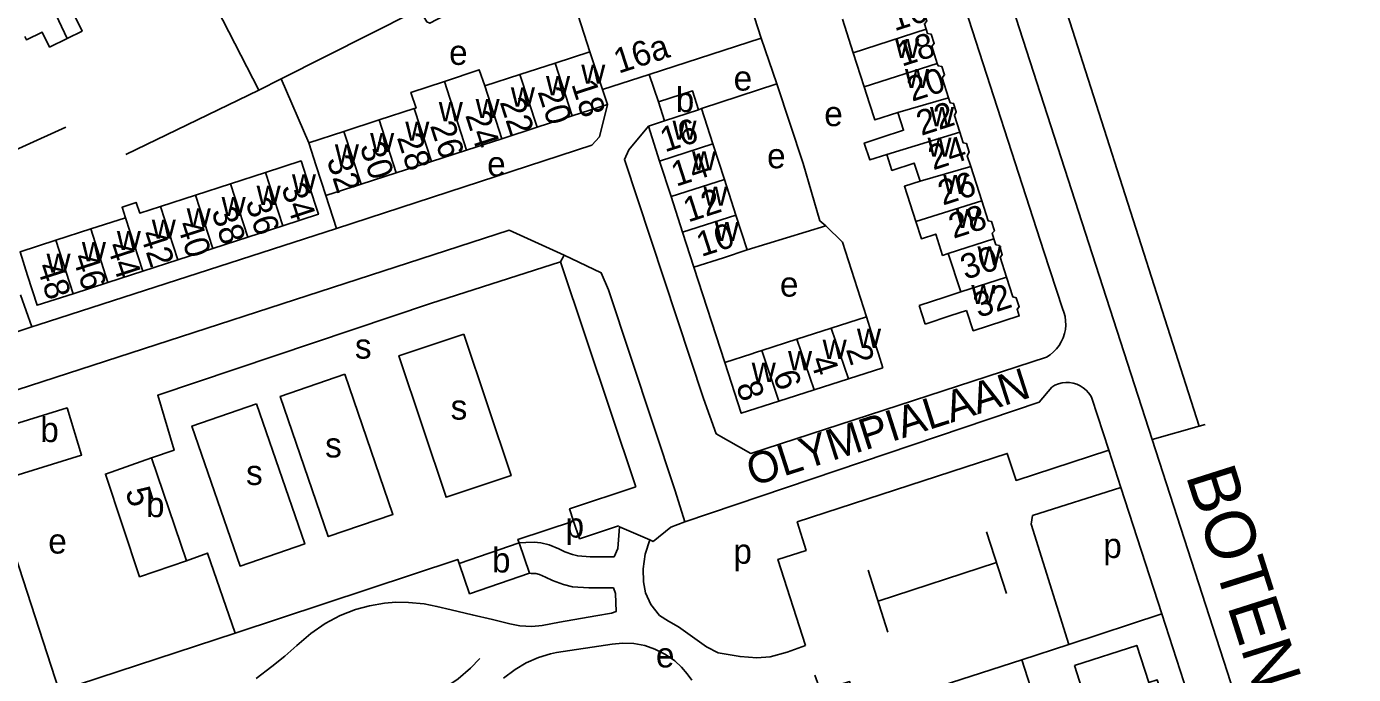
# Model space of a CAD drawing. Extents: x 157569 to 159501, y 382907 to 384670.
# Drawn here: x 159236.8 to 159450, y 383198.5 to 383302.6 of the extents above; entities that cross this region are included whole.
import ezdxf

# ---------------------------------------------------------------- set-up
doc = ezdxf.new("R2010")
doc.units = 0
for name, color, linetype in [('BLT_Basislijn', 7, 'Continuous'), ('BLT_Bebouwing', 7, 'Continuous'), ('BLT_Centroide', 7, 'Continuous'), ('BLT_Huisnummer', 7, 'Continuous'), ('BLT_Huisnummer_ tussenligend', 7, 'Continuous'), ('BLT_Onderverdeling_panden', 7, 'Continuous'), ('BLT_Straatnaam', 7, 'Continuous'), ('BLT_Straatnaam_hoofdweg', 7, 'Continuous'), ('BLT_Vlakafsluiter', 7, 'Continuous')]:
    doc.layers.add(name, color=color, linetype=linetype)

msp = doc.modelspace()

# ---------------------------------------------------------------- linework, layer by layer
at = {"layer": 'BLT_Basislijn'}
for p, q in [((159379.54, 383354.13), (159408.56, 383264.22)), ((159376.06, 383341.3), (159400.22, 383266.41)), ((159425.15, 383238.36), (159395.57, 383330.94)), ((159264.77, 383310.5), (159274.09, 383292.35)), ((159354.8, 383300.68), (159357.32, 383293.39)), ((159338.28, 383290.45), (159336.8, 383294.86)), ((159252.74, 383282.03), (159274.09, 383292.35)), ((159277.69, 383294.17), (159274.09, 383292.35)), ((159277.69, 383294.17), (159282.11, 383283.9)), ((159357.32, 383293.39), (159345.21, 383289.38)), ((159284.86, 383275.41), (159286.59, 383270.15)), ((159352.52, 383266.71), (159365.2, 383270.54)), ((159322.54, 383264.76), (159323.12, 383265.83)), ((159400.22, 383266.41), (159403.2, 383257.26)), ((159343.98, 383263.9), (159348.96, 383248.6)), ((159408.56, 383264.22), (159417.61, 383236.25)), ((159237.62, 383254.3), (159235.8, 383259.46)), ((159192.4, 383239.63), (159237.62, 383254.3)), ((159407.94, 383242.87), (159410.65, 383234.51)), ((159417.61, 383236.25), (159437.39, 383175.1)), ((159410.65, 383234.51), (159412.59, 383228.53)), ((159412.59, 383228.53), (159419.16, 383208.22)), ((159394.22, 383211.51), (159390.99, 383221.39)), ((159373.57, 383210.25), (159392.61, 383216.45)), ((159371.98, 383215.21), (159375.17, 383205.29)), ((159404.23, 383203.27), (159419.16, 383208.22)), ((159419.16, 383208.22), (159427.45, 383182.63)), ((159396.7, 383200.83), (159404.23, 383203.27)), ((159396.7, 383200.83), (159404.81, 383175.08))]:
    msp.add_line(p, q, dxfattribs=at)
for points in [[(159322.28, 383313.99), (159301.55, 383303.11), (159301.08, 383303.33), (159300.1, 383304.91), (159299.07, 383304.91), (159277.69, 383294.17)], [(159357.32, 383293.39), (159361.54, 383280.58), (159364.22, 383271.37), (159365.2, 383270.54)], [(159286.59, 383270.15), (159327.57, 383283.52), (159328.82, 383284.86), (159330.08, 383290.04)], [(159243.1, 383286.39), (159229.71, 383280.36), (159228.83, 383279.98)], [(159336.67, 383286.59), (159333.53, 383282.75), (159332.82, 383281.2), (159345.53, 383242.79)], [(159227.11, 383241.57), (159314.29, 383269.88), (159323.12, 383265.83)], [(159237.62, 383254.3), (159238.66, 383254.64), (159286.59, 383270.15)], [(159365.2, 383270.54), (159367.88, 383267.95), (159371.72, 383255.94)], [(159256.84, 383233.29), (159260.47, 383234.5), (159257.84, 383243.34), (159301.65, 383258.08), (159322.54, 383264.76)], [(159334.65, 383228.6), (159322.54, 383264.76)], [(159323.12, 383265.83), (159329.1, 383262.99), (159330.27, 383260.28), (159340.96, 383227.96), (159342.53, 383222.99)], [(159400.62, 383249.48), (159401.21, 383249.85), (159401.75, 383250.29), (159402.24, 383250.79), (159402.66, 383251.34), (159403.02, 383251.93), (159403.32, 383252.57), (159403.53, 383253.23), (159403.67, 383253.91), (159403.73, 383254.6), (159403.71, 383255.3), (159403.61, 383255.99), (159403.43, 383256.66), (159403.2, 383257.26)], [(159307.05, 383253.15), (159314.61, 383230.43), (159304.16, 383226.95), (159296.6, 383249.67), (159307.05, 383253.15)], [(159345.53, 383242.79), (159347.54, 383237.16), (159353.11, 383233.98), (159400.62, 383249.48)], [(159287.93, 383246.7), (159295.63, 383224.17), (159285.25, 383220.62), (159277.54, 383243.15), (159287.93, 383246.7)], [(159401.47, 383244.66), (159401.99, 383244.95), (159402.55, 383245.17), (159403.13, 383245.31), (159403.73, 383245.38), (159404.33, 383245.36), (159404.92, 383245.27), (159405.49, 383245.1), (159406.04, 383244.85), (159406.54, 383244.53), (159407.01, 383244.15), (159407.41, 383243.71), (159407.75, 383243.22), (159407.94, 383242.87)], [(159401.47, 383244.66), (159399.46, 383242.2), (159342.53, 383222.99)], [(159227.11, 383241.57), (159242, 383195.83)], [(159273.73, 383241.94), (159281.46, 383219.46), (159271.07, 383215.88), (159263.33, 383238.37), (159273.73, 383241.94)], [(159410.65, 383234.51), (159395.75, 383229.65), (159394.33, 383234), (159360.6, 383222.99), (159362, 383218.41), (159357.49, 383216.95), (159361.94, 383203.13)], [(159324.65, 383223.12), (159324.01, 383225.06), (159334.65, 383228.6)], [(159404.23, 383203.27), (159398.17, 383222.63), (159398.4, 383223.99), (159412.59, 383228.53)], [(159315.9, 383219.6), (159315.71, 383220.16), (159324.65, 383223.12)], [(159324.65, 383223.12), (159325.62, 383220.27), (159331.87, 383222.34)], [(159331.75, 383218.71), (159332.06, 383222.2)], [(159331.87, 383222.34), (159332.06, 383222.2)], [(159332.06, 383222.2), (159336.92, 383220.08)], [(159337.46, 383219.85), (159340.3, 383222.12), (159342.53, 383222.99)], [(159331.75, 383218.71), (159331.17, 383217.37), (159327.3, 383217.37), (159325.33, 383217.52), (159324.47, 383217.74), (159323.25, 383218.16), (159322.3, 383218.66), (159320.75, 383219.31), (159319.37, 383219.63), (159318.34, 383219.72), (159316.96, 383219.68), (159315.9, 383219.6)], [(159336.92, 383220.08), (159336.14, 383217.79), (159335.82, 383215.46), (159335.89, 383213.38), (159336.23, 383211.57), (159337.08, 383209.7), (159338.45, 383207.97), (159339.93, 383207.03), (159341.54, 383206.13), (159345.99, 383202.89)], [(159336.92, 383220.08), (159337.46, 383219.85)], [(159262.48, 383216.74), (159265.86, 383217.99), (159270.27, 383205.11)], [(159270.27, 383205.11), (159306.06, 383216.96), (159306.29, 383216.3)], [(159331.41, 383211.48), (159331.07, 383212.37), (159327.11, 383212.37), (159324.5, 383212.56), (159323.02, 383212.95), (159321.27, 383213.55), (159320.17, 383214.13), (159319.2, 383214.54), (159318.58, 383214.68), (159318.2, 383214.71), (159317.84, 383214.7), (159317.57, 383214.75)], [(159273.68, 383197.83), (159276.2, 383199.73), (159278.26, 383201.4), (159280.22, 383203.12), (159282.47, 383205.08), (159284.77, 383206.66), (159287.18, 383207.93), (159289.62, 383208.89), (159291.87, 383209.51), (159294.3, 383209.92), (159296.09, 383210.07), (159298.16, 383210.06), (159300.64, 383209.82), (159302.69, 383209.42), (159305, 383208.87), (159308.38, 383208.07), (159311.65, 383207.29), (159314.4, 383206.63), (159316.04, 383206.3), (159317.95, 383206.2), (159319.6, 383206.36), (159322.38, 383206.86), (159328.24, 383207.89), (159330.73, 383208.3), (159331.51, 383208.61), (159331.41, 383211.48)], [(159242, 383195.83), (159270.27, 383205.11)], [(159313.38, 383197.88), (159315.25, 383199.3), (159317.03, 383200.33), (159319.02, 383201.2), (159320.96, 383201.79), (159321.93, 383201.99), (159330.86, 383203.37), (159332.49, 383203.52), (159334.36, 383203.44), (159336.08, 383203.11), (159337.71, 383202.56), (159339.45, 383201.68), (159340.91, 383200.64), (159342.01, 383199.63), (159342.91, 383198.58), (159343.63, 383197.56)], [(159361.94, 383203.13), (159358.99, 383202.07), (159356.24, 383201.33), (159354.12, 383201.15), (159351.4, 383201.34), (159347.86, 383201.96), (159345.99, 383202.89)], [(159281.32, 383196.59), (159283.97, 383195.19), (159287.47, 383194.01), (159291.12, 383193.43), (159294.66, 383193.44), (159298.77, 383194.14), (159301.59, 383195.19), (159303.96, 383196.35), (159306.09, 383197.79), (159308.09, 383199.47), (159309.58, 383201.02)], [(159363.44, 383198.36), (159364.34, 383195.82), (159369, 383197.34), (159370.57, 383192.4), (159396.7, 383200.83)]]:
    msp.add_lwpolyline(points, dxfattribs=at)
at = {"layer": 'BLT_Bebouwing'}
for p, q in [((159346.57, 383326.35), (159354.8, 383300.68)), ((159327.29, 383298.52), (159322.28, 383313.99)), ((159336.8, 383294.86), (159354.8, 383300.68)), ((159321.68, 383296.7), (159327.29, 383298.52)), ((159316.03, 383294.88), (159321.68, 383296.7)), ((159310.38, 383293.05), (159316.03, 383294.88)), ((159329.33, 383292.44), (159336.8, 383294.86)), ((159330.08, 383290.04), (159329.33, 383292.44)), ((159324.43, 383288.21), (159330.08, 383290.04)), ((159338.28, 383290.45), (159339.25, 383287.42)), ((159293.42, 383287.56), (159299.07, 383289.39)), ((159318.78, 383286.38), (159324.43, 383288.21)), ((159344.75, 383289.21), (159345.21, 383289.38)), ((159345.21, 383289.38), (159347.04, 383283.71)), ((159282.11, 383283.9), (159287.77, 383285.73)), ((159287.77, 383285.73), (159293.42, 383287.56)), ((159313.13, 383284.55), (159318.78, 383286.38)), ((159336.67, 383286.59), (159339.25, 383287.42)), ((159338.48, 383280.96), (159336.67, 383286.59)), ((159307.47, 383282.73), (159313.13, 383284.55)), ((159347.04, 383283.71), (159348.88, 383278)), ((159301.82, 383280.9), (159307.47, 383282.73)), ((159296.17, 383279.07), (159301.82, 383280.9)), ((159340.32, 383275.24), (159338.48, 383280.96)), ((159390.25, 383274.56), (159388.46, 383280.08)), ((159269.53, 383277.31), (159263.92, 383275.49)), ((159275.15, 383279.13), (159269.53, 383277.31)), ((159284.86, 383275.41), (159290.51, 383277.24)), ((159290.51, 383277.24), (159296.17, 383279.07)), ((159348.88, 383278), (159350.72, 383272.29)), ((159263.92, 383275.49), (159258.31, 383273.68)), ((159342.16, 383269.53), (159340.32, 383275.24)), ((159252.69, 383271.86), (159247.08, 383270.05)), ((159350.72, 383272.29), (159352.52, 383266.71)), ((159247.08, 383270.05), (159241.46, 383268.23)), ((159272.31, 383268.74), (159266.69, 383266.92)), ((159277.92, 383270.55), (159272.31, 383268.74)), ((159343.98, 383263.9), (159342.16, 383269.53)), ((159266.69, 383266.92), (159261.08, 383265.1)), ((159261.08, 383265.1), (159255.47, 383263.29)), ((159384.85, 383266.09), (159386.85, 383259.93)), ((159255.47, 383263.29), (159249.85, 383261.47)), ((159249.85, 383261.47), (159244.24, 383259.65)), ((159384.33, 383259.1), (159380.2, 383257.74)), ((159366.04, 383254.11), (159371.72, 383255.94)), ((159380.2, 383257.74), (159381.14, 383254.78)), ((159381.14, 383254.78), (159385.28, 383256.14)), ((159360.52, 383252.34), (159366.04, 383254.11)), ((159354.89, 383250.52), (159360.52, 383252.34)), ((159368.83, 383245.98), (159374.34, 383247.76)), ((159363.33, 383244.22), (159368.83, 383245.98)), ((159357.61, 383242.37), (159363.33, 383244.22)), ((159262.48, 383216.74), (159256.84, 383233.29)), ((159315.9, 383219.6), (159306.29, 383216.3))]:
    msp.add_line(p, q, dxfattribs=at)
for points in [[(159381.29, 383302.14), (159381.02, 383303.01), (159381.41, 383303.45), (159380.94, 383304.93), (159380.39, 383305.04), (159379.54, 383307.67)], [(159243.32, 383300.66), (159245.7, 383301.83), (159244.62, 383304.01), (159247.36, 383305.32)], [(159369.57, 383298.35), (159367.86, 383303.77)], [(159236.49, 383300.99), (159236.74, 383300.44), (159239.27, 383301.68), (159240.47, 383299.26), (159243.32, 383300.66)], [(159383.09, 383296.63), (159382.19, 383299.41), (159382.59, 383299.86), (159382.12, 383301.34), (159381.51, 383301.47), (159381.29, 383302.14)], [(159371.35, 383292.89), (159369.57, 383298.35)], [(159384.89, 383291.11), (159383.85, 383294.34), (159384.26, 383294.8), (159383.83, 383296.13), (159383.21, 383296.26), (159383.09, 383296.63)], [(159303.91, 383293.75), (159309.51, 383295.63), (159310.38, 383293.05)], [(159299.07, 383289.39), (159299.35, 383289.48), (159298.52, 383291.99), (159303.91, 383293.75)], [(159344.75, 383289.21), (159343.78, 383292.22), (159338.28, 383290.45)], [(159376.75, 383288.76), (159373.08, 383287.56), (159372.21, 383290.21), (159371.35, 383292.89)], [(159386.69, 383285.6), (159385.83, 383288.26), (159386.15, 383288.87), (159385.71, 383290.21), (159385.15, 383290.33), (159384.89, 383291.11)], [(159374.98, 383282.02), (159372.23, 383281.15), (159371.35, 383283.86), (159374.1, 383284.75), (159377.68, 383285.91), (159376.75, 383288.76)], [(159284.86, 383275.41), (159283.32, 383280.17), (159282.11, 383283.9)], [(159388.46, 383280.08), (159387.9, 383281.8), (159388.22, 383282.41), (159387.77, 383283.8), (159387.24, 383283.91), (159386.69, 383285.6)], [(159380.33, 383277.74), (159379.39, 383280.63), (159375.81, 383279.46), (159374.98, 383282.02)], [(159277.92, 383270.55), (159283.65, 383272.41), (159282.12, 383277.16), (159280.88, 383280.98), (159275.15, 383279.13)], [(159379.65, 383271.26), (159377.82, 383276.92), (159380.33, 383277.74)], [(159258.31, 383273.68), (159254.96, 383272.6), (159254.36, 383274.32), (159252.12, 383273.55), (159252.69, 383271.86)], [(159392.2, 383268.47), (159391.91, 383269.36), (159392.28, 383269.77), (159391.81, 383271.23), (159391.29, 383271.35), (159390.25, 383274.56)], [(159384.85, 383266.09), (159383.95, 383265.8), (159382.84, 383269.24), (159380.55, 383268.49), (159379.65, 383271.26)], [(159244.24, 383259.65), (159238.47, 383257.79), (159236.93, 383262.55), (159235.73, 383266.37), (159241.46, 383268.23)], [(159352.52, 383266.71), (159348.74, 383265.43), (159343.98, 383263.9)], [(159394.21, 383262.31), (159393.18, 383265.5), (159393.54, 383265.9), (159393.06, 383267.39), (159392.51, 383267.51), (159392.2, 383268.47)], [(159387.8, 383256.97), (159388.86, 383253.7), (159396.25, 383256.09), (159395.91, 383257.16), (159396.26, 383257.55), (159395.79, 383259.01), (159395.25, 383259.12), (159394.21, 383262.31)], [(159386.85, 383259.93), (159384.33, 383259.1)], [(159374.34, 383247.76), (159373.62, 383250), (159372.81, 383252.52), (159371.72, 383255.94)], [(159385.28, 383256.14), (159387.8, 383256.97)], [(159354.89, 383250.52), (159354.06, 383250.26), (159353.72, 383250.14), (159353.32, 383250), (159348.96, 383248.6)], [(159348.96, 383248.6), (159351.59, 383240.43), (159357.61, 383242.37)], [(159232.37, 383237.93), (159243.27, 383241.29), (159245.6, 383233.72), (159234.71, 383230.36), (159232.37, 383237.93)], [(159256.84, 383233.29), (159249.45, 383230.66), (159254.93, 383214.18), (159262.48, 383216.74)], [(159317.57, 383214.75), (159315.9, 383219.6)], [(159306.29, 383216.3), (159307.96, 383211.44), (159317.57, 383214.75)], [(159405.12, 383199.89), (159407.07, 383193.86), (159409.1, 383187.37), (159411.09, 383181.24), (159421.18, 383184.51), (159419.23, 383190.54), (159420.58, 383190.95), (159418.43, 383197.6), (159417.08, 383197.17), (159415.15, 383203.14), (159405.12, 383199.89)]]:
    msp.add_lwpolyline(points, dxfattribs=at)
at = {"layer": 'BLT_Onderverdeling_panden'}
for p, q in [((159238.23, 383311.37), (159243.32, 383300.66)), ((159381.29, 383302.14), (159369.57, 383298.35)), ((159327.29, 383298.52), (159329.33, 383292.44)), ((159324.43, 383288.21), (159321.68, 383296.7)), ((159383.09, 383296.63), (159371.35, 383292.89)), ((159318.78, 383286.38), (159316.03, 383294.88)), ((159307.47, 383282.73), (159303.91, 383293.75)), ((159313.13, 383284.55), (159310.38, 383293.05)), ((159384.89, 383291.11), (159376.75, 383288.76)), ((159301.82, 383280.9), (159299.07, 383289.39)), ((159339.25, 383287.42), (159344.75, 383289.21)), ((159290.51, 383277.24), (159287.77, 383285.73)), ((159296.17, 383279.07), (159293.42, 383287.56)), ((159338.48, 383280.96), (159347.04, 383283.71)), ((159386.69, 383285.6), (159374.98, 383282.02)), ((159388.46, 383280.08), (159380.33, 383277.74)), ((159272.31, 383268.74), (159269.53, 383277.31)), ((159277.92, 383270.55), (159275.15, 383279.13)), ((159340.32, 383275.24), (159348.88, 383278)), ((159266.69, 383266.92), (159263.92, 383275.49)), ((159261.08, 383265.1), (159258.31, 383273.68)), ((159390.25, 383274.56), (159379.65, 383271.26)), ((159255.47, 383263.29), (159252.69, 383271.86)), ((159342.16, 383269.53), (159350.72, 383272.29)), ((159249.85, 383261.47), (159247.08, 383270.05)), ((159244.24, 383259.65), (159241.46, 383268.23)), ((159392.2, 383268.47), (159384.85, 383266.09)), ((159394.21, 383262.31), (159386.85, 383259.93)), ((159368.83, 383245.98), (159366.04, 383254.11)), ((159363.33, 383244.22), (159360.52, 383252.34)), ((159357.61, 383242.37), (159354.89, 383250.52))]:
    msp.add_line(p, q, dxfattribs=at)
at = {"layer": 'BLT_Vlakafsluiter'}
for q in [(159417.61, 383236.25), (159426.14, 383238.66)]:
    msp.add_line((159425.15, 383238.36), q, dxfattribs=at)

# ---------------------------------------------------------------- texts
at = {"layer": 'BLT_Centroide'}
for s, p in [('e', (159304.66, 383296.41)), ('w', (159376.32, 383297.5)), ('w', (159325.89, 383293.38)), ('w', (159320.23, 383291.53)), ('e', (159350.37, 383292.28)), ('w', (159377.89, 383292.69)), ('w', (159314.58, 383289.72)), ('b', (159341.07, 383288.82)), ('w', (159303, 383287.36)), ('w', (159308.92, 383287.88)), ('e', (159364.93, 383286.57)), ('w', (159381.92, 383286.56)), ('w', (159297.62, 383284.22)), ('w', (159340.55, 383284.38)), ('w', (159286.31, 383280.56)), ('w', (159291.97, 383282.41)), ('w', (159381.52, 383281.66)), ('e', (159310.77, 383278.51)), ('w', (159343.68, 383279.47)), ('e', (159355.75, 383279.8)), ('w', (159279.41, 383275.77)), ('w', (159384.05, 383275.66)), ('w', (159268.11, 383272.11)), ('w', (159273.73, 383273.92)), ('w', (159345.52, 383273.78)), ('w', (159262.5, 383270.3)), ('w', (159386.08, 383270.19)), ('w', (159256.89, 383268.48)), ('w', (159347.35, 383268.09)), ('w', (159251.27, 383266.67)), ('w', (159245.66, 383264.86)), ('w', (159389.54, 383264.19)), ('w', (159239.98, 383263.02)), ('e', (159357.81, 383259.18)), ('w', (159388.55, 383258)), ('w', (159370.19, 383250.94)), ('s', (159289.53, 383249.22)), ('w', (159364.67, 383249.17)), ('w', (159359.11, 383247.36)), ('w', (159353.28, 383245.48)), ('s', (159304.91, 383239.42)), ('b', (159238.98, 383235.81)), ('s', (159284.74, 383233.34)), ('s', (159272.04, 383228.92)), ('b', (159255.97, 383223.75)), ('p', (159323.37, 383220.47)), ('e', (159240.26, 383217.9)), ('p', (159409.76, 383217.19)), ('b', (159311.55, 383214.86)), ('p', (159350.33, 383216.27)), ('e', (159337.89, 383199.61))]:
    msp.add_text(s, height=4, dxfattribs=at).set_placement(p)
at = {"layer": 'BLT_Huisnummer'}
for s, rotation, p in [('18', 17.9336, (159377.4, 383296.1)), ('16a', 17.9259, (159331.88, 383294.98)), ('18', 287.9274, (159324.26, 383293.32)), ('22', 287.9254, (159312.76, 383290.45)), ('22', 17.9274, (159380.52, 383285)), ('16', 17.8585, (159339.33, 383282.34)), ('26', 287.9254, (159301.56, 383286.67)), ('30', 287.9271, (159290.27, 383283.33)), ('34', 287.9224, (159277.67, 383276.73)), ('26', 17.9306, (159383.98, 383273.79)), ('38', 287.9244, (159266.44, 383272.88)), ('10', 17.8516, (159345.17, 383265.53)), ('42', 287.9244, (159254.97, 383269.26)), ('46', 287.935, (159244.11, 383265.54)), ('32', 17.9312, (159389.7, 383255.74)), ('2', 287.8488, (159368.39, 383250.72)), ('8', 287.8477, (159350.73, 383244.91)), ('5', 287.1357, (159252.61, 383227.94))]:
    msp.add_text(s, height=4, rotation=rotation, dxfattribs=at).set_placement(p)
at = {"layer": 'BLT_Huisnummer_ tussenligend'}
for s, rotation, p in [('16', 17.9296, (159376.21, 383301.79)), ('20', 17.9336, (159379.03, 383290.47)), ('20', 287.9274, (159318.85, 383292.12)), ('24', 287.9254, (159307.22, 383288.33)), ('28', 287.9254, (159296.24, 383284.74)), ('24', 17.9274, (159382.43, 383279.45)), ('32', 287.9271, (159284.95, 383281.18)), ('14', 17.8516, (159341.12, 383276.82)), ('36', 287.9224, (159271.92, 383274.38)), ('12', 17.8516, (159343.06, 383271.08)), ('28', 17.9306, (159385.69, 383268.46)), ('40', 287.9244, (159260.9, 383270.76)), ('44', 287.9244, (159249.65, 383267.36)), ('30', 17.9306, (159387.6, 383261.86)), ('48', 287.935, (159238.37, 383264.04)), ('4', 287.8488, (159362.63, 383249.03)), ('6', 287.8488, (159356.67, 383246.69))]:
    msp.add_text(s, height=4, rotation=rotation, dxfattribs=at).set_placement(p)
at = {"layer": 'BLT_Straatnaam'}
msp.add_text('OLYMPIALAAN', height=5, rotation=17.7421, dxfattribs=at).set_placement((159353.43, 383228.69))
at = {"layer": 'BLT_Straatnaam_hoofdweg'}
msp.add_text('BOTENLAAN', height=8, rotation=287.627, dxfattribs=at).set_placement((159422.97, 383230.47))

doc.saveas('drawing.dxf')
